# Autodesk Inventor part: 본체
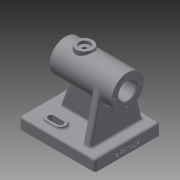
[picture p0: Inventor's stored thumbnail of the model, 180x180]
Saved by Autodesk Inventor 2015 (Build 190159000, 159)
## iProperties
Created: 2022-06
Part Number: 본체
Material: 일반
Document SubType Name: Modeling
Designer: 10415
Density: 1 g/cm^3
Appearance: 기본값
Author: 10415
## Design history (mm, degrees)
sketch "스케치1"
  geometry: L1 (50, -43)-(-50, -43); L2 (-50, -43)-(-50, 43); L3 (-50, 43)-(50, 43); L4 (50, 43)-(50, -43); L5 (50, -43)-(-50, 43); L6 (-50, -43)-(50, 43); 1 further point
  constraints: 12 end point, 2 midpoint, 2 parallel, 1 horizontal, 1 perpendicular
  dimensions: "d0" = 100 distance of L2.end L3.end; "d1" = 86 distance of L1.end L2.end
extrude "돌출1" new body sketch "스케치1" distance "d2" = 15; taper "d3" = 0 deg
sketch "스케치5"
  geometry: L1 (-50, -43)-(50, -43) reference; L2 (50, -43)-(50, 43) reference; L3 (-50, 43)-(-50, -43) reference; L4 (-35, 5)-(35, 5); L5 (35, 5)-(35, -5); L6 (35, -5)-(-35, -5); L7 (-35, -5)-(-35, 5); 1 further point
  constraints: 8 end point, 2 parallel, 1 horizontal, 1 perpendicular
  dimensions: "d18" = 15 distance between parallel lines of L2 L5; "d20" = 15 distance between parallel lines of L3 L7; "d21" = 10 distance of L4.end L5.end; "d22" = 38 distance between parallel lines of L1 L6
extrude "돌출3" join sketch "스케치5" distance "d23" = 57; taper "d24" = 0 deg
feature "면 기울기2" dims angle "d27" = 20 deg
sketch "스케치6"
  geometry: L1 (32, 93)-(-50, 93); L2 (-50, 93)-(-50, 72); L3 (-50, 72)-(32, 72); L4 (32, 72)-(32, 93); L5 (-50, 0)-(-50, 15) reference; L6 (-50, 15)-(-35, 15) reference; L7 (-35, 15)-(-35, 72) reference; L8 (-35, 72)-(14.254, 72) reference; L9 (14.254, 72)-(35, 15) reference; L10 (35, 15)-(50, 15) reference; L11 (50, 15)-(50, 0) reference; L12 (50, 0)-(-50, 0) reference; 1 further point
  constraints: 8 end point, 2 collinear, 2 parallel, 1 horizontal, 1 perpendicular
  dimensions: "d25" = 21 distance of L1.end L2.end; "d26" = 82 distance of L1.start L1.end
revolve "회전2" sketch "스케치6" stored, may be unused: angle "d28" = 90 deg
sketch "스케치7"
  geometry: L1 (15, -38)-(0, -38) reference; L2 (0, -38)-(0, 0) reference; L3 (0, 0)-(-36.604, 0) reference; L4 (-36.604, 10)-(0, 10) reference; L5 (0, 10)-(0, 48) reference; L6 (0, 48)-(15, 48) reference; L7 (15, 48)-(15, -38) reference; L8 (0, 0)-(0, 10) reference; L9 (0, -30)-(-61.814, -15.441); L10 (-61.814, 25.441)-(0, 40); L11 (0, 10)-(-36.604, 10) reference; A1 r 21 centre (-57, 5) between (-36.604, 0) and (-36.604, 10) reference; A2 r 21 centre (-57, 5) between (-36.604, 10) and (-36.604, 0) reference; A3 r 21 centre (-57, 5) between (-36.604, 0) and (-36.604, 10) reference; 1 further point
  constraints: 4 end point, 2 point on circle, 2 point on line, 2 tangent
  dimensions: "d29" = 8 distance from line of L1 L9.start; "d30" = 8 distance from line of L6 L10.end
  node "절단 모서리 투영3"
sketch "스케치8"
  geometry: C1 r 21 at (0, 0) reference; C2 r 14.5 at (0, 0); 1 further point
  constraints: 1 centre point, 1 coincident
  dimensions: "d33" = 29 diameter of C2
extrude "돌출5" cut sketch "스케치8" distance "d34" = 62; taper "d35" = 0 deg
sketch "스케치9"
  geometry: C1 r 14.5 at (0, 0) reference; C2 r 11.5 at (0, 0); 1 further point
  constraints: 1 centre point, 1 coincident
  dimensions: "d36" = 23 diameter of C2
extrude "돌출6" cut sketch "스케치9" stored distance "d37" = 62; taper "d38" = 0 deg
extrude "돌출7" join sketch "스케치7" distance "d41" = 10; taper "d42" = 0 deg
node "작업 평면3"
sketch "스케치10"
  geometry: L1 (-32, 21)-(-32, -21) reference; C1 r 11 at (-7, 0); 1 further point
  constraints: 1 centre point, 1 horizontal alignment
  dimensions: "d44" = 22 diameter of C1; "d45" = 25 distance from line of L1 C1.centre
extrude "돌출8" join sketch "스케치10" stored distance "d46" = 10; taper "d47" = 0 deg
sketch "스케치11"
  geometry: C1 r 11 at (0, 0) reference; 1 further point
hole "구멍1" sketch "스케치11" at (0, 0) diameter "d48" = 4.917; stored, may be unused: countersink angle "d52" = 90 deg, drill point angle "d54" = 118 deg; dims "d49" = 12, "d50" = 14, "d51" = 4, "d53" = 21
sketch "스케치12"
  geometry: C1 r 11.5 at (0, 0) reference; 2 further points
  constraints: 1 horizontal alignment
  dimensions: "d55" = 18 distance of C1.centre point (-18, 0)
hole "구멍2" sketch "스케치12" at (-18, 0) diameter "d56" = 2.459; stored, may be unused: countersink angle "d60" = 90 deg, drill point angle "d62" = 118 deg; dims "d57" = 8, "d58" = 14, "d59" = 4, "d61" = 10
node "작업 평면4"
sketch "스케치13"
  geometry: L1 (-50, -43)-(50, -43) reference; L2 (-50, 43)-(-50, -43) reference; L3 (-24, -27)-(-12, -27); L4 (-24, -34)-(-12, -34); L5 (-12, -20)-(-24, -20); A1 r 7 centre (-24, -27) between (-24, -20) and (-24, -34); A2 r 7 centre (-12, -27) between (-12, -34) and (-12, -20); 2 further points
  constraints: 8 end point, 4 point on circle, 4 tangent, 2 centre point, 1 horizontal, 1 midpoint, 1 parallel
  dimensions: "d66" = 26 distance from line of L2 L3.start; "d67" = 12 distance of L3.start L3.end; "d68" = 16 distance from line of L1 L3.start; "d69" = 14 distance between parallel lines of L4 L5
extrude "돌출9" join sketch "스케치13" distance "d70" = 3; taper "d71" = 0 deg
sketch "스케치14"
  geometry: L1 (-12, -27)-(-24, -27); L2 (-12, -23)-(-24, -23); L3 (-24, -31)-(-12, -31); A1 r 7 centre (-12, -27) between (-12, -34) and (-12, -20) reference; A2 r 7 centre (-24, -27) between (-24, -20) and (-24, -34) reference; A3 r 4 centre (-12, -27) between (-12, -31) and (-12, -23); A4 r 4 centre (-24, -27) between (-24, -23) and (-24, -31); 2 further points
  constraints: 8 end point, 4 point on circle, 4 tangent, 2 centre point, 1 horizontal, 1 midpoint, 1 parallel
  dimensions: "d72" = 8 diameter of A4
extrude "돌출10" cut sketch "스케치14" stored distance "d73" = 3; taper "d74" = 0 deg
fillet "모깎기1" dims "d75" = 3
fillet "모깎기2" dims "d76" = 3
fillet "모깎기3" dims "d77" = 1
chamfer "모따기1" distance "d78" = 1; stored, may be unused: second distance "d79" = 2, angle "d80" = 45 deg
sketch "스케치15"
  geometry: L1 (0, 80)-(0, 0) reference; 3 further points
  constraints: 1 horizontal alignment, 1 midpoint, 1 other
  dimensions: "d81" = 6 distance from line of L1 point (-6, 40)
feature "엠보싱1" sketch "스케치15" dims "d0" = 100, "d1" = 86, "d82" = 0.5, "d83" = 0
fillet "모깎기4" dims "d84" = 3
fillet "모깎기5" dims "d85" = 3
node "솔리드1"
pattern_circular "원형 패턴1" dims angle "d64" = 360 deg
mirror "대칭1"
mirror "대칭2"
node "절단 모서리 투영2"
other parameters: "d43" = 96
